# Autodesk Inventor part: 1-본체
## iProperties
Created: 2015-02
Part Number: 1-본체
Material: 알루미늄-6061
Document SubType Name: Modeling
Designer: elite
Mass: 752.13 g
Surface Area: 838.032 cm^2
Volume: 277.539 cm^3
Density: 2.71 g/cm^3
Author: elite
